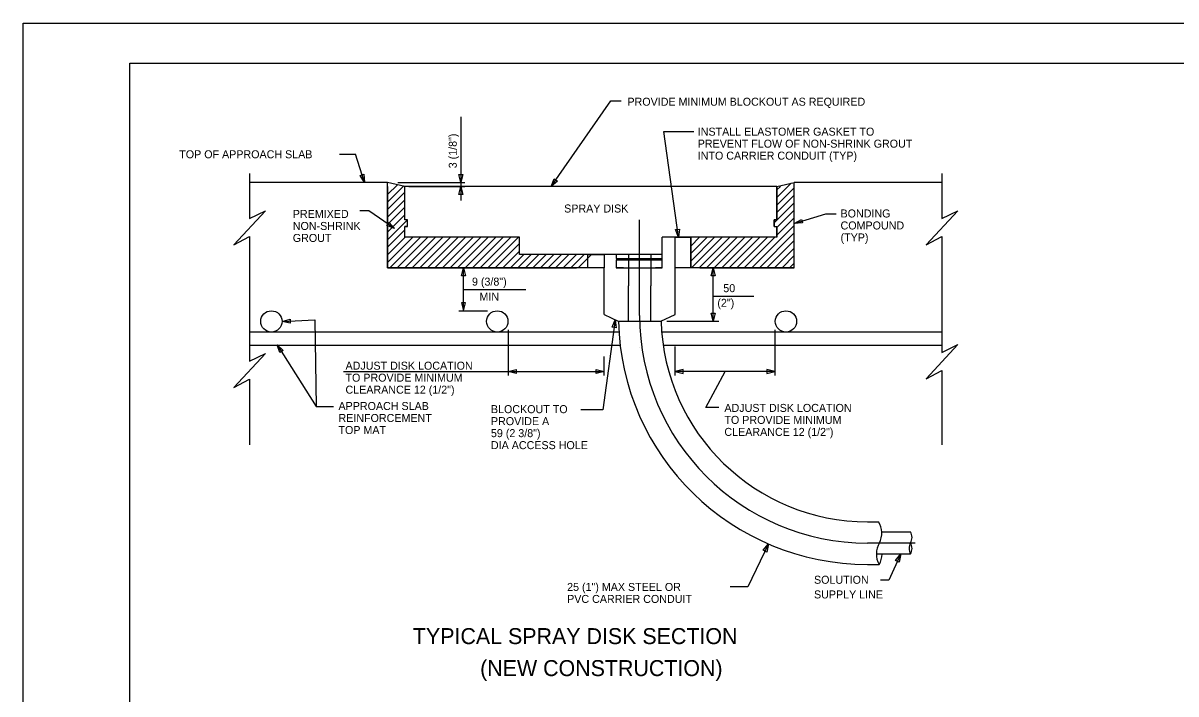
# Model space of a CAD drawing. Extents: x 3239 to 4230, y -4276 to -2494.
# Drawn here: x 3239 to 3671.4, y -2746 to -2494.3 of the extents above; entities that cross this region are included whole.
import ezdxf

# ---------------------------------------------------------------- set-up
doc = ezdxf.new("R2010")
doc.units = 0
doc.layers.add('2', color=7, linetype='Continuous')
doc.layers.add('PLT-BNDY', color=7, linetype='Continuous')

msp = doc.modelspace()

# ---------------------------------------------------------------- linework, layer by layer
at = {"layer": '2'}
for p, q in [((3279.03, -3073.29), (3279.03, -2509.29)), ((3279.03, -2509.29), (4065.03, -2509.29)), ((3403.16, -2529.52), (3403.16, -2560.81)), ((3357.75, -2543.52), (3363.75, -2543.52)), ((3367.03, -2554.12), (3363.75, -2543.52)), ((3323.88, -2550.73), (3323.88, -2567.63)), ((3583.57, -2550.73), (3583.57, -2567.63)), ((3375.75, -2554.12), (3323.88, -2554.12)), ((3382.25, -2555.62), (3375.75, -2554.12)), ((3375.75, -2586.12), (3375.75, -2554.12)), ((3375.75, -2558.6), (3379.38, -2554.96)), ((3379.53, -2554.12), (3404.66, -2554.12)), ((3521.75, -2555.62), (3528.25, -2554.12)), ((3521.75, -2559.73), (3527.09, -2554.39)), ((3528.25, -2586.12), (3528.25, -2554.12)), ((3583.57, -2554.12), (3528.25, -2554.12)), ((3375.75, -2561.43), (3381.55, -2555.62)), ((3375.75, -2555.62), (3375.75, -2586.12)), ((3375.75, -2555.77), (3375.9, -2555.62)), ((3375.75, -2564.26), (3382.25, -2557.76)), ((3382.25, -2568.12), (3382.25, -2555.62)), ((3521.75, -2555.62), (3382.25, -2555.62)), ((3382.25, -2568.12), (3382.25, -2555.62)), ((3383.75, -2555.62), (3404.66, -2555.62)), ((3521.75, -2568.12), (3521.75, -2555.62)), ((3521.75, -2555.62), (3521.75, -2568.12)), ((3521.75, -2556.9), (3523.03, -2555.62)), ((3521.75, -2562.56), (3528.25, -2556.06)), ((3521.75, -2565.39), (3528.25, -2558.89)), ((3528.25, -2586.12), (3528.25, -2555.62)), ((3375.75, -2567.09), (3382.25, -2560.59)), ((3375.75, -2569.91), (3382.25, -2563.41)), ((3520.75, -2569.22), (3528.25, -2561.72)), ((3329.92, -2564.72), (3318.01, -2577.51)), ((3323.88, -2567.63), (3329.92, -2564.72)), ((3368.72, -2564.78), (3365.34, -2564.78)), ((3378.33, -2571.36), (3368.72, -2564.78)), ((3375.75, -2572.74), (3382.25, -2566.24)), ((3521.75, -2571.04), (3528.25, -2564.54)), ((3521.75, -2573.87), (3528.25, -2567.37)), ((3589.6, -2564.72), (3577.7, -2577.51)), ((3583.57, -2567.63), (3589.6, -2564.72)), ((3375.75, -2575.57), (3383.2, -2568.12)), ((3375.75, -2578.4), (3382.25, -2571.9)), ((3383.25, -2568.12), (3382.25, -2568.12)), ((3383.25, -2568.12), (3382.25, -2568.12)), ((3383.25, -2570.62), (3382.25, -2570.62)), ((3382.25, -2574.62), (3382.25, -2570.62)), ((3382.25, -2574.62), (3382.25, -2570.62)), ((3382.25, -2570.62), (3383.25, -2570.62)), ((3383.25, -2570.62), (3383.25, -2568.12)), ((3383.25, -2570.62), (3383.25, -2568.12)), ((3470.25, -2603.94), (3470.25, -2568.09)), ((3512.33, -2586.12), (3528.25, -2570.2)), ((3520.75, -2568.12), (3521.75, -2568.12)), ((3520.75, -2570.62), (3520.75, -2568.12)), ((3521.75, -2568.12), (3520.75, -2568.12)), ((3520.75, -2568.12), (3520.75, -2570.62)), ((3520.75, -2570.62), (3521.75, -2570.62)), ((3520.75, -2570.62), (3521.75, -2570.62)), ((3521.75, -2574.62), (3521.75, -2570.62)), ((3521.75, -2570.62), (3521.75, -2574.62)), ((3318.01, -2577.51), (3323.88, -2574.38)), ((3323.88, -2574.38), (3323.88, -2621.14)), ((3375.75, -2581.23), (3382.35, -2574.62)), ((3375.75, -2584.06), (3385.18, -2574.62)), ((3376.51, -2586.12), (3388.01, -2574.62)), ((3379.34, -2586.12), (3390.84, -2574.62)), ((3382.17, -2586.12), (3393.67, -2574.62)), ((3425.25, -2574.62), (3382.25, -2574.62)), ((3425.25, -2574.62), (3382.25, -2574.62)), ((3384.99, -2586.12), (3396.49, -2574.62)), ((3387.82, -2586.12), (3399.32, -2574.62)), ((3390.65, -2586.12), (3402.15, -2574.62)), ((3393.48, -2586.12), (3404.98, -2574.62)), ((3396.31, -2586.12), (3407.81, -2574.62)), ((3399.14, -2586.12), (3410.64, -2574.62)), ((3401.97, -2586.12), (3413.47, -2574.62)), ((3404.79, -2586.12), (3416.29, -2574.62)), ((3407.62, -2586.12), (3419.12, -2574.62)), ((3410.45, -2586.12), (3421.95, -2574.62)), ((3413.28, -2586.12), (3424.78, -2574.62)), ((3425.25, -2581.12), (3425.25, -2574.62)), ((3425.25, -2581.12), (3425.25, -2574.62)), ((3521.75, -2574.62), (3478.75, -2574.62)), ((3478.75, -2586.12), (3478.75, -2574.62)), ((3489.4, -2586.12), (3489.4, -2574.62)), ((3489.4, -2577.93), (3492.71, -2574.62)), ((3489.4, -2580.76), (3495.54, -2574.62)), ((3489.4, -2583.59), (3498.37, -2574.62)), ((3489.7, -2586.12), (3501.2, -2574.62)), ((3521.75, -2574.62), (3491.6, -2574.62)), ((3492.53, -2586.12), (3504.03, -2574.62)), ((3495.35, -2586.12), (3506.85, -2574.62)), ((3498.18, -2586.12), (3509.68, -2574.62)), ((3501.01, -2586.12), (3512.51, -2574.62)), ((3503.84, -2586.12), (3515.34, -2574.62)), ((3506.67, -2586.12), (3518.17, -2574.62)), ((3509.5, -2586.12), (3521, -2574.62)), ((3515.15, -2586.12), (3528.25, -2573.03)), ((3517.98, -2586.12), (3528.25, -2575.86)), ((3577.7, -2577.51), (3583.57, -2574.38)), ((3583.57, -2574.38), (3583.57, -2603.96)), ((3416.11, -2586.12), (3425.25, -2576.98)), ((3418.94, -2586.12), (3425.25, -2579.81)), ((3520.81, -2586.12), (3528.25, -2578.69)), ((3421.76, -2586.12), (3426.76, -2581.12)), ((3424.59, -2586.12), (3429.59, -2581.12)), ((3478.75, -2581.12), (3425.25, -2581.12)), ((3448.89, -2581.12), (3425.25, -2581.12)), ((3427.42, -2586.12), (3432.42, -2581.12)), ((3430.25, -2586.12), (3435.25, -2581.12)), ((3433.08, -2586.12), (3438.08, -2581.12)), ((3435.91, -2586.12), (3440.91, -2581.12)), ((3438.73, -2586.12), (3443.73, -2581.12)), ((3441.56, -2586.12), (3446.56, -2581.12)), ((3444.39, -2586.12), (3449.39, -2581.12)), ((3447.19, -2586.12), (3452.19, -2581.12)), ((3461.5, -2581.12), (3461.5, -2582.62)), ((3461.5, -2582.62), (3478.75, -2582.62)), ((3461.5, -2583.12), (3478.75, -2583.12)), ((3461.5, -2583.12), (3461.5, -2586.12)), ((3466.1, -2581.12), (3466.1, -2582.62)), ((3466.1, -2583.12), (3466.1, -2592.87)), ((3474.4, -2581.12), (3474.4, -2582.62)), ((3474.4, -2583.12), (3474.4, -2592.87)), ((3523.64, -2586.12), (3528.25, -2581.51)), ((3526.47, -2586.12), (3528.25, -2584.34)), ((3375.75, -2586.12), (3446.55, -2586.12)), ((3456.92, -2586.12), (3375.75, -2586.12)), ((3404.23, -2602.23), (3404.23, -2586.12)), ((3456.92, -2603.62), (3456.92, -2586.12)), ((3464.25, -2586.12), (3461.5, -2586.12)), ((3461.5, -2586.12), (3478.75, -2586.12)), ((3464.25, -2586.12), (3476.25, -2586.12)), ((3476.25, -2586.12), (3478.75, -2586.12)), ((3478.75, -2586.12), (3476.25, -2586.12)), ((3483.57, -2603.62), (3483.57, -2586.12)), ((3493.95, -2586.12), (3483.57, -2586.12)), ((3528.25, -2586.12), (3483.57, -2586.12)), ((3492.87, -2586.12), (3499.5, -2586.12)), ((3493.95, -2586.12), (3528.25, -2586.12)), ((3497.86, -2606.12), (3497.86, -2586.12)), ((3466.1, -2606.12), (3466.1, -2592.87)), ((3474.4, -2606.12), (3474.4, -2592.87)), ((3404.23, -2594.18), (3427.51, -2594.18)), ((3497.86, -2596.75), (3513.04, -2596.75)), ((3402.4, -2602.23), (3413.16, -2602.23)), ((3461.05, -2605.56), (3456.48, -2639.44)), ((3456.92, -2603.62), (3462.25, -2606.12)), ((3462.25, -2606.12), (3478.25, -2606.12)), ((3478.25, -2606.12), (3483.57, -2603.62)), ((3480.39, -2606.12), (3499.89, -2606.12)), ((3583.57, -2603.96), (3583.57, -2617.84)), ((3462.46, -2610.25), (3323.88, -2610.25)), ((3420.95, -2609.41), (3420.95, -2626.56)), ((3583.57, -2610.25), (3478.5, -2610.25)), ((3520.99, -2609.41), (3520.99, -2626.56)), ((3462.93, -2615.25), (3323.88, -2615.25)), ((3583.57, -2615.25), (3479.08, -2615.25)), ((3483.57, -2626.56), (3483.57, -2615.57)), ((3589.6, -2614.93), (3577.7, -2627.71)), ((3583.57, -2617.84), (3589.6, -2614.93)), ((3329.92, -2618.24), (3318.01, -2631.02)), ((3323.88, -2621.14), (3329.92, -2618.24)), ((3456.92, -2626.56), (3456.92, -2619.38)), ((3318.01, -2631.02), (3323.88, -2627.89)), ((3323.88, -2627.89), (3323.88, -2652.49)), ((3359.19, -2625.06), (3456.92, -2625.06)), ((3520.99, -2625.06), (3483.57, -2625.06)), ((3495.1, -2638.55), (3502.28, -2625.06)), ((3577.7, -2627.71), (3583.57, -2624.58)), ((3583.57, -2624.58), (3583.57, -2652.49)), ((3456.48, -2639.44), (3448.19, -2639.44)), ((3499.93, -2638.55), (3495.1, -2638.55)), ((3555.69, -2681.38), (3559.78, -2681.38)), ((3561.03, -2685.15), (3571.83, -2685.15)), ((3518.57, -2689.7), (3510.8, -2705.78)), ((3573.53, -2689.38), (3555.69, -2689.38)), ((3555.69, -2697.38), (3560.04, -2697.38)), ((3559.02, -2693.46), (3571.83, -2693.46)), ((3510.8, -2705.78), (3504.18, -2705.78))]:
    msp.add_line(p, q, dxfattribs=at)
for points in [[(3437.05, -2555.62), (3459.43, -2523.53), (3463.37, -2523.53)], [(3484.83, -2574.62), (3479.36, -2534.99), (3490.54, -2534.99)], [(3528.25, -2569.51), (3540.12, -2565.81), (3544, -2565.81)], [(3336.17, -2606.23), (3348.43, -2605.58), (3348.98, -2638.09)], [(3334.36, -2614.96), (3348.98, -2638.09), (3348.98, -2638.09), (3355.45, -2638.09)], [(3568.2, -2693.46), (3563.63, -2703.26), (3560.53, -2703.26)]]:
    msp.add_lwpolyline(points, dxfattribs=at)
for points in [[(3366.86, -2551.03), (3367.03, -2554.12), (3365.43, -2551.48)], [(3403.91, -2551.12), (3403.16, -2554.12), (3402.41, -2551.12)], [(3439.38, -2553.59), (3437.05, -2555.62), (3438.15, -2552.73)], [(3402.41, -2558.62), (3403.16, -2555.62), (3403.91, -2558.62)], [(3531.3, -2569.23), (3528.25, -2569.51), (3530.92, -2568)], [(3376.28, -2569.05), (3378.33, -2571.36), (3375.43, -2570.28)], [(3485.17, -2571.55), (3484.83, -2574.62), (3483.68, -2571.75)], [(3483.57, -2574.62), (3489.4, -2574.62), (3489.4, -2586.12), (3483.57, -2586.12)], [(3450.84, -2581.12), (3456.92, -2581.12), (3456.92, -2586.12), (3450.84, -2586.12)], [(3403.48, -2589.12), (3404.23, -2586.12), (3404.98, -2589.12)], [(3497.11, -2589.12), (3497.86, -2586.12), (3498.61, -2589.12)], [(3403.48, -2599.23), (3404.23, -2602.23), (3404.98, -2599.23)], [(3339.21, -2606.82), (3336.17, -2606.23), (3339.13, -2605.32)], [(3459.91, -2608.43), (3461.05, -2605.56), (3461.39, -2608.63)], [(3498.61, -2603.12), (3497.86, -2606.12), (3497.11, -2603.12)], [(3335.33, -2617.9), (3334.36, -2614.96), (3336.59, -2617.1)], [(3423.95, -2625.81), (3420.95, -2625.06), (3423.95, -2624.31)], [(3453.92, -2624.31), (3456.92, -2625.06), (3453.92, -2625.81)], [(3486.57, -2624.31), (3483.57, -2625.06), (3486.57, -2625.81)], [(3517.99, -2625.81), (3520.99, -2625.06), (3517.99, -2624.31)], [(3516.59, -2692.07), (3518.57, -2689.7), (3517.94, -2692.72)], [(3566.25, -2695.86), (3568.2, -2693.46), (3567.61, -2696.5)]]:
    msp.add_lwpolyline(points, close=True, dxfattribs=at)
for centre in [(3332.17, -2606.23), (3416.85, -2606.23), (3525.09, -2606.23)]:
    msp.add_circle(centre, 4, dxfattribs=at)
for centre, radius, start, end in [((3555.69, -2603.94), 93.44, 181.336, 270), ((3555.69, -2603.94), 85.44, 180, 270), ((3555.69, -2603.94), 77.44, 181.6121, 270), ((3450.25, -2616.16), 20, 0, 2.777777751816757e-06), ((3553.11, -2685.67), 7.93, 332.7154, 32.7154), ((3568.23, -2687.23), 4.16, 330, 30), ((3567.09, -2693.45), 8.08, 149.1201, 209.1201), ((3575.43, -2691.38), 4.16, 150, 210), ((3568.23, -2691.38), 4.16, 330, 30), ((3553.1, -2693.24), 8.08, 329.1201, 358.4019)]:
    msp.add_arc(centre, radius, start, end, dxfattribs=at)
at = {"layer": 'PLT-BNDY'}
msp.add_lwpolyline([(3239.03, -2494.29), (4080.03, -2494.29), (4080.03, -3088.29), (3239.03, -3088.29)], close=True, dxfattribs=at)

# ---------------------------------------------------------------- texts
at = {"layer": '2'}
for s, height, p in [('PROVIDE MINIMUM BLOCKOUT AS REQUIRED', 3, (3465.67, -2525.3)), ('INSTALL ELASTOMER GASKET TO ', 3, (3492.03, -2536.53)), ('TOP OF APPROACH SLAB', 3, (3297.6, -2545.02)), ('PREVENT FLOW OF NON-SHRINK GROUT', 3, (3492.03, -2541.03)), ('INTO CARRIER CONDUIT (TYP)', 3, (3492.03, -2545.53)), ('SPRAY DISK', 3, (3441.94, -2565.36)), ('PREMIXED', 3, (3340.18, -2567.4)), ('BONDING', 3, (3545.58, -2567.22)), ('NON-SHRINK', 3, (3340.18, -2571.9)), ('COMPOUND', 3, (3545.58, -2571.72)), ('GROUT', 3, (3340.18, -2576.4)), ('(TYP)', 3, (3545.58, -2576.22)), ('9 (3/8")', 3, (3407.37, -2592.79)), ('50', 3, (3501.62, -2595.24)), ('MIN ', 3, (3410.17, -2598.43)), ('(2")', 3, (3499.39, -2600.74)), ('ADJUST DISK LOCATION', 3, (3359.94, -2624.32)), ('TO PROVIDE MINIMUM', 3, (3359.94, -2628.82)), ('CLEARANCE 12 (1/2")', 3, (3359.94, -2633.32)), ('APPROACH SLAB', 3, (3357.31, -2639.45)), ('ADJUST DISK LOCATION', 3, (3502.03, -2640.16)), ('REINFORCEMENT', 3, (3357.31, -2643.95)), ('BLOCKOUT TO', 3, (3414.48, -2640.63)), ('TOP MAT', 3, (3357.31, -2648.45)), ('PROVIDE A ', 3, (3414.48, -2645.13)), ('TO PROVIDE MINIMUM', 3, (3502.03, -2644.66)), ('59 (2 3/8")', 3, (3414.48, -2649.63)), ('CLEARANCE 12 (1/2")', 3, (3502.03, -2649.16)), ('DIA ACCESS HOLE', 3, (3414.48, -2654.13)), ('SOLUTION', 3, (3535.63, -2704.63)), ('25 (1") MAX STEEL OR', 3, (3443.05, -2707.32)), ('PVC CARRIER CONDUIT', 3, (3443.05, -2711.82)), ('SUPPLY LINE', 3, (3535.63, -2710.13)), ('TYPICAL SPRAY DISK SECTION', 6, (3385.21, -2727.27)), ('(NEW CONSTRUCTION)', 6, (3410.42, -2739.27))]:
    msp.add_text(s, height=height, dxfattribs=at).set_placement(p)
msp.add_text('3 (1/8")', height=3, rotation=90, dxfattribs=at).set_placement((3401.66, -2548.77))

doc.saveas('drawing.dxf')
